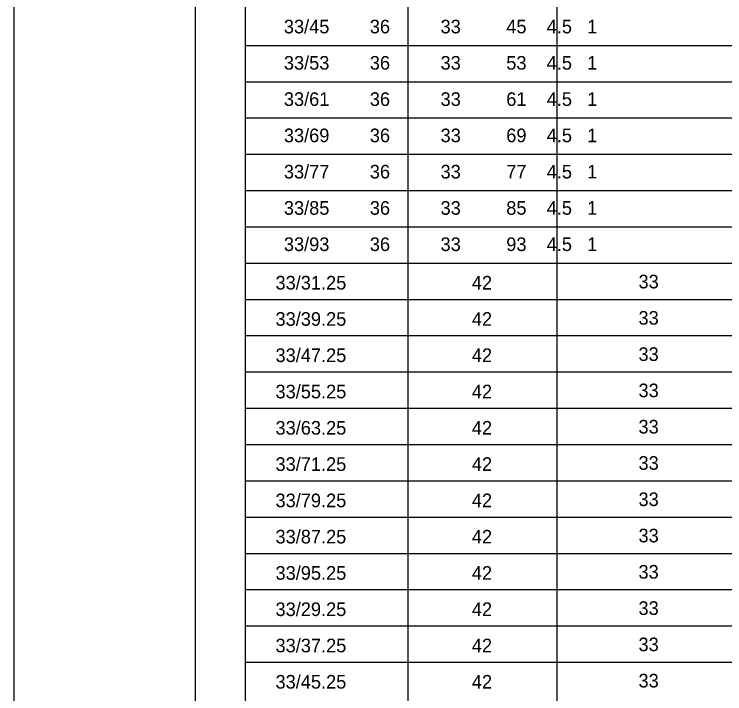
# Model space of a CAD drawing. Extents: x 635698 to 639877, y 296617 to 300175.
# Drawn here: x 638802.3 to 638959, y 298558.4 to 298708.2 of the extents above; entities that cross this region are included whole.
import ezdxf

# ---------------------------------------------------------------- set-up
doc = ezdxf.new("R2010")
doc.units = 0
for name, color, linetype in [('1', 7, 'Continuous'), ('2', 7, 'Continuous'), ('PLT-BNDY', 7, 'Continuous')]:
    doc.layers.add(name, color=color, linetype=linetype)

msp = doc.modelspace()

# ---------------------------------------------------------------- linework, layer by layer
at = {"layer": '2'}
for p, q in [((638842.3, 298272.8), (638842.3, 298836.8)), ((638853.27, 298826.88), (638853.27, 298509.29)), ((638889.15, 298814.79), (638889.15, 298581.29)), ((638922.02, 298814.79), (638922.02, 298581.29)), ((639405.11, 298701.29), (638853.27, 298701.29)), ((639405.11, 298693.29), (638853.27, 298693.29)), ((639405.11, 298685.29), (638853.27, 298685.29)), ((639405.11, 298677.29), (638853.27, 298677.29)), ((639405.11, 298669.29), (638853.27, 298669.29)), ((639405.11, 298661.29), (638853.27, 298661.29)), ((639405.11, 298653.29), (638853.27, 298653.29)), ((639405.11, 298645.29), (638853.27, 298645.29)), ((639405.11, 298637.29), (638853.27, 298637.29)), ((639405.11, 298629.29), (638853.27, 298629.29)), ((639405.11, 298621.29), (638853.27, 298621.29)), ((639405.11, 298613.29), (638853.27, 298613.29)), ((639405.11, 298605.29), (638853.27, 298605.29)), ((639405.11, 298597.29), (638853.27, 298597.29)), ((639405.11, 298589.29), (638853.27, 298589.29)), ((639405.11, 298581.29), (638853.27, 298581.29)), ((639405.11, 298581.29), (638853.27, 298581.29)), ((638889.15, 298581.29), (638889.15, 298509.29)), ((638922.02, 298581.29), (638922.02, 298509.29)), ((639405.11, 298573.29), (638853.27, 298573.29)), ((639405.11, 298565.29), (638853.27, 298565.29))]:
    msp.add_line(p, q, dxfattribs=at)
at = {"layer": 'PLT-BNDY'}
msp.add_lwpolyline([(638802.3, 298851.8), (639643.3, 298851.8), (639643.3, 298257.8), (638802.3, 298257.8)], close=True, dxfattribs=at)

# ---------------------------------------------------------------- texts
at = {"layer": '1'}
for s, p in [(' 33/45        36          33         45    4.5   1  ', (638860.67, 298704.02)), (' 33/53        36          33         53    4.5   1  ', (638860.67, 298696.02)), (' 33/61        36          33         61    4.5   1  ', (638860.67, 298688.02)), (' 33/69        36          33         69    4.5   1  ', (638860.67, 298680.02)), (' 33/77        36          33         77    4.5   1  ', (638860.67, 298672.02)), (' 33/85        36          33         85    4.5   1  ', (638860.67, 298664.02)), (' 33/93        36          33         93    4.5   1  ', (638860.67, 298656.02))]:
    msp.add_text(s, height=3, dxfattribs=at).set_placement(p)
at = {"layer": '2'}
for s, p in [('33', (638940.01, 298647.79)), ('33/31.25', (638859.94, 298647.54)), ('42', (638903.25, 298647.54)), ('33/39.25', (638859.94, 298639.54)), ('42', (638903.25, 298639.54)), ('33', (638940.01, 298639.79)), ('33/47.25', (638859.94, 298631.54)), ('42', (638903.25, 298631.54)), ('33', (638940.01, 298631.79)), ('33/55.25', (638859.94, 298623.54)), ('42', (638903.25, 298623.54)), ('33', (638940.01, 298623.79)), ('33/63.25', (638859.94, 298615.54)), ('42', (638903.25, 298615.54)), ('33', (638940.01, 298615.79)), ('33/71.25', (638859.94, 298607.54)), ('42', (638903.25, 298607.54)), ('33', (638940.01, 298607.79)), ('33/79.25', (638859.94, 298599.54)), ('42', (638903.25, 298599.54)), ('33', (638940.01, 298599.79)), ('33/87.25', (638859.94, 298591.54)), ('42', (638903.25, 298591.54)), ('33', (638940.01, 298591.79)), ('33/95.25', (638859.94, 298583.54)), ('42', (638903.25, 298583.54)), ('33', (638940.01, 298583.79)), ('33', (638940.01, 298575.79)), ('33/29.25', (638859.94, 298575.54)), ('42', (638903.25, 298575.54)), ('33/37.25', (638859.94, 298567.54)), ('42', (638903.25, 298567.54)), ('33', (638940.01, 298567.79)), ('33/45.25', (638859.94, 298559.54)), ('42', (638903.25, 298559.54)), ('33', (638940.01, 298559.79))]:
    msp.add_text(s, height=3, dxfattribs=at).set_placement(p)

doc.saveas('drawing.dxf')
